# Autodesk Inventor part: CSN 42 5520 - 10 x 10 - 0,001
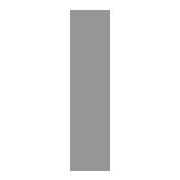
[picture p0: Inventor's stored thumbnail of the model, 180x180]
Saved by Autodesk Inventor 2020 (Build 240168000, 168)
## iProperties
Created: 2019-01
Part Number: CSN 42 5520 - 10 x 10 - 0,001
Material: Ocel, měkká
Description: Tyč
Document SubType Name: Modeling
Standard: CSN 42 5520
Designer: doma
Standards Organization: CSN
Language: cs-CZ
Size Designation: 10 x 10 - 0,001
Categories: <MemberInstance><Categories><Category DisplayName="Konstrukční profily" InternalName="089c4875-fa83-4c05-b084-43b9cc11f5ed" Mnemonic="GRDR"><CategoryParameter D
Stock Number: 10 x 10
Density: 7.85 g/cm^3
Appearance: Pololeštěná
Mass: 187.889 g
Surface Area: 98.234 cm^2
Volume: 23.9348 cm^3
IsCustomPart: 1
G_L: 0,001 mm
Author: doma
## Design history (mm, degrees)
node "Počáteční rovina"
node "Koncová rovina"
sketch "Náčrt"
  geometry: L1 (5, -5)-(-5, -5); L2 (-5, -5)-(-5, 5); L3 (-5, 5)-(5, 5); L4 (5, 5)-(5, -5); L5 (-6, 0)-(8, 0); L6 (0, -30)-(0, 40); L7 (0, 54)-(0, -44) reference; L8 (-9.2, 0)-(13.2, 0) reference
  constraints: 12 end point, 2 collinear, 2 parallel, 1 horizontal, 1 perpendicular
  dimensions: "d0" = 10 distance between parallel lines of L3 L1 (= G_W); "d1" = 10 distance between parallel lines of L4 L2 (= G_H); "d4" = 5 distance between parallel lines of L6 L4 (= 0.5 x d1); "d5" = 5 distance between parallel lines of L5 L3 (= 0.5 x d0)
extrude "Těleso" new body sketch "Náčrt" stored distance "d2" = 245; taper "d3" = 0 deg
node "Driven Length"
  sketch "Sketch3"
    geometry: L1 (0, 0)-(10, 0) reference
    constraints: 2 end point, 1 horizontal
  workplane "Work Plane3"
  sketch "Sketch4"
    geometry: L1 (-2, 0)-(12, 0) reference; L2 (-2, 0.001)-(12, 0.001) reference
    dimensions: "d9" = 0.001 distance between parallel lines of L1 L2 (derived)
sketch "Náčrt6"
  geometry: L1 (0, 0)-(2.837, 10) reference; L2 (2.837, 10)-(3.442, 17.316); L3 (3.442, 17.316)-(-24.382, 8.144); L4 (-24.382, 8.144)-(-3.153, -2.986); L5 (0, 0)-(0, 10) reference; L6 (-3.153, -2.986)-(0, 0); L7 (245.277, 7)-(238.355, 0) reference; L8 (245, 0)-(245, 10) reference; L9 (245, 8)-(235, 8); L10 (235, 8)-(235, 10); L11 (0, 10)-(245, 10) reference; L12 (245, 0)-(240.283, -3.67); L13 (240.283, -3.67)-(238.355, 0); C1 r 64 at (245.277, 73.75) reference; 2 further points
  constraints: 16 end point, 2 point on line, 1 horizontal, 1 perpendicular
  dimensions: "d11" = 10 distance of L9.start L9.end; "d12" = 2 distance of L9.end L10.end
extrude "Vysunutí2" cut sketch "Náčrt6" extent not by distance; stored distance "d13" = 0; taper "d14" = 0 deg
chamfer "Zkosení1" distance "d15" = 2; stored, may be unused: second distance "d16" = 2, angle "d17" = 45 deg
body "Solid1"
node "Referenční1"
node "Referenční2"
node "Referenční3"
other parameters: "G_W" = 10 [user parameter; used in 1 equation term], "G_H" = 10 [user parameter; used in 1 equation term], "G_L" = 0.001 (= d9) [user parameter], "G_OFFSET_START" = 0 [user parameter; used in 1 equation term], "G_OFFSET_END" = 0 [user parameter; used in 1 equation term], "d6" = 0 (computed from G_OFFSET_START), "d7" = 0.001 (= G_OFFSET_END + B_L), "B_L" = 0.001 [user parameter; used in 1 equation term], "d8" = 90 deg
